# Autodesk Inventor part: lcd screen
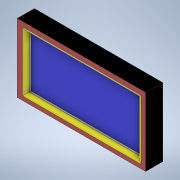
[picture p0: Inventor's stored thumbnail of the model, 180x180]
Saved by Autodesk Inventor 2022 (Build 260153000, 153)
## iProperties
Created: 2021-06
Part Number: lcd screen
Material: Generic
Document SubType Name: Modeling
Designer: Dell
Density: 1 g/cm^3
Appearance: Default
Author: Dell
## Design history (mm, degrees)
sketch "Sketch1"
  geometry: L1 (-65.896, 37.71)-(9.104, 37.71); L2 (9.104, 37.71)-(9.104, -2.29); L3 (9.104, -2.29)-(-65.896, -2.29); L4 (-65.896, -2.29)-(-65.896, 37.71); 1 further point
  constraints: 8 end point, 2 parallel, 1 horizontal, 1 perpendicular
  dimensions: "d0" = 75 distance of L2.end L3.end; "d1" = 40 distance of L1.end L2.end
extrude "Extrusion1" new body sketch "Sketch1" distance "d2" = 10; taper "d3" = 0 deg
sketch "Sketch2"
  geometry: L1 (-60.843, 2.013)-(4.49, 2.013); L2 (4.49, 2.013)-(4.49, 32.976); L3 (4.49, 32.976)-(-60.843, 32.976); L4 (-60.843, 32.976)-(-60.843, 2.013); 1 further point
  constraints: 8 end point, 2 parallel, 1 horizontal, 1 perpendicular
extrude "Extrusion2" cut sketch "Sketch2" distance "d4" = 3; taper "d5" = 0 deg
fillet "Fillet1" dims "d6" = 2
body "Solid1"
